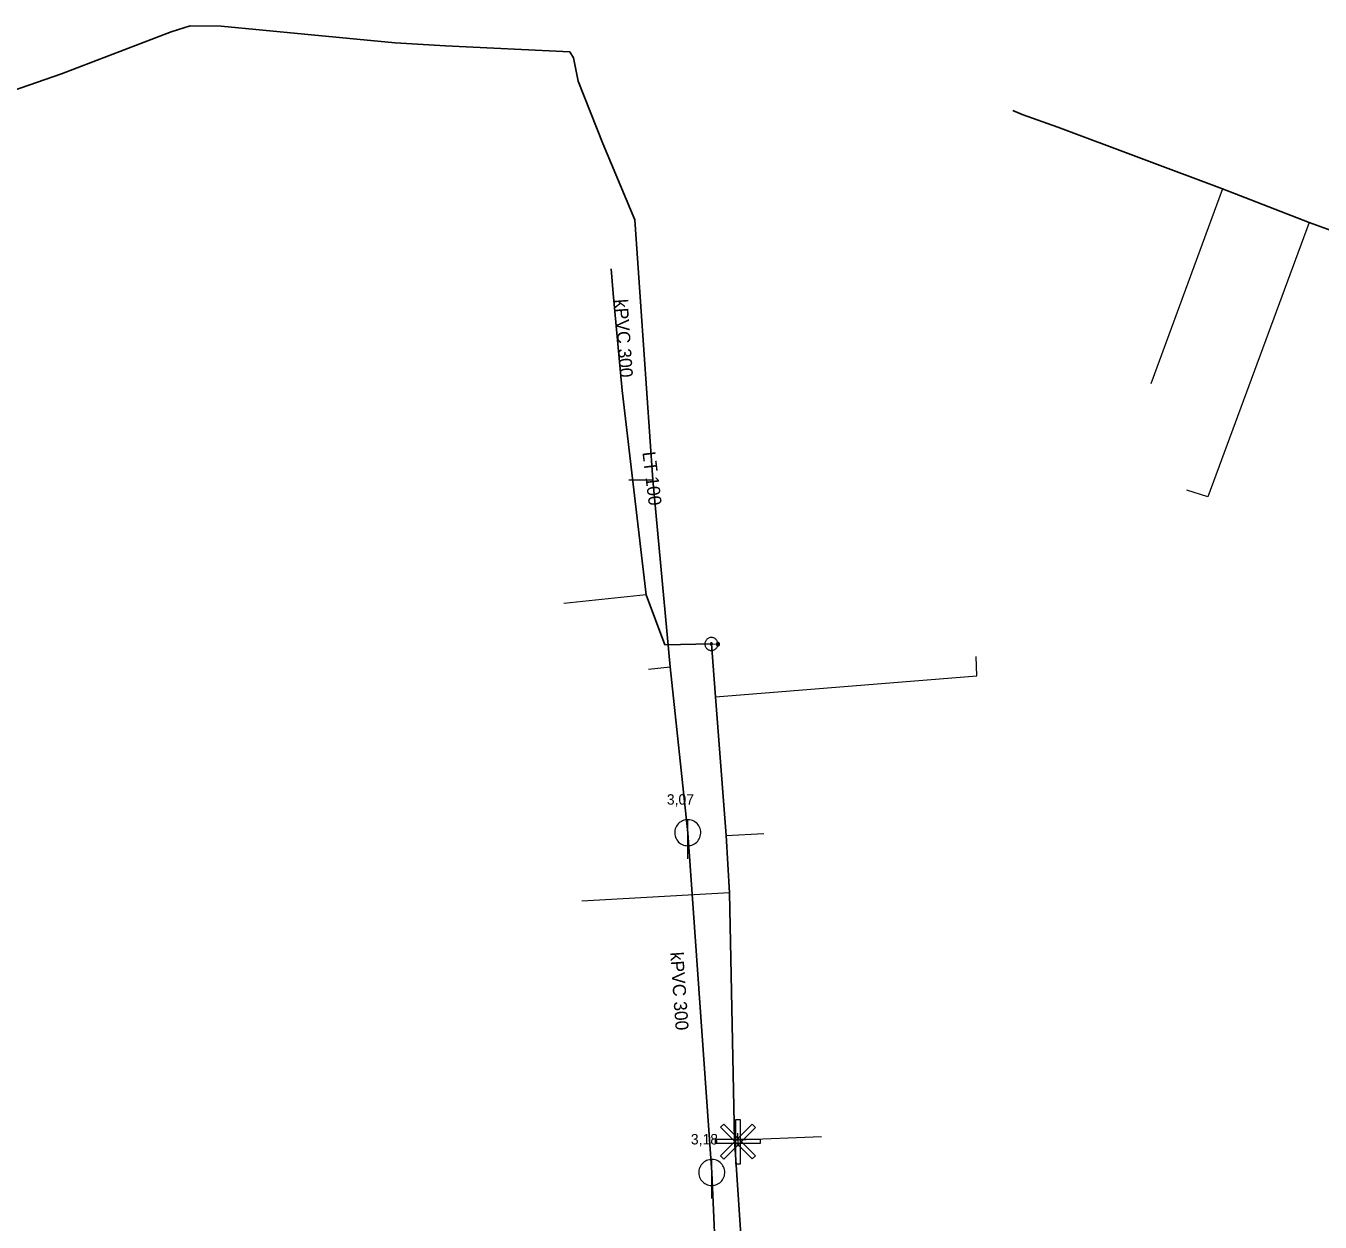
# Model space of a CAD drawing. Extents: x -809916 to -809489, y -991143 to -990912.
# Drawn here: x -809721.2 to -809621.9, y -991005.4 to -990913.7 of the extents above; entities that cross this region are included whole.
import ezdxf

# ---------------------------------------------------------------- set-up
doc = ezdxf.new("R2010")
doc.units = 0
doc.header["$LTSCALE"] = 0.32
doc.layers.add('1', color=7, linetype='Continuous')
for name, color, linetype, lineweight in [('11', 7, 'Continuous', 13), ('12', 7, 'Continuous', 13), ('13', 7, 'Continuous', 13), ('14', 7, 'Continuous', 25), ('17', 7, 'Continuous', 25), ('22', 7, 'Continuous', 13), ('34', 7, 'Continuous', 13), ('47', 7, 'Continuous', 13), ('9', 7, 'Continuous', 13)]:
    doc.layers.add(name, color=color, linetype=linetype, lineweight=lineweight)

msp = doc.modelspace()

# ---------------------------------------------------------------- linework, layer by layer
at = {"layer": '11'}
for p, q in [((-809674.932, -990948.515), (-809673.085, -990948.515)), ((-809673.438, -990963.031), (-809671.767, -990962.855))]:
    msp.add_line(p, q, dxfattribs=at)
at = {"layer": '12'}
for points in [[(-809666.74, -990997.569), (-809666.39, -990997.569), (-809666.39, -991001.004), (-809666.74, -991001.004)], [(-809665.474, -990997.933), (-809665.226, -990998.181), (-809667.655, -991000.61), (-809667.902, -991000.362)], [(-809667.893, -990998.172), (-809667.646, -990997.924), (-809665.217, -991000.353), (-809665.464, -991000.601)], [(-809664.856, -990999.078), (-809664.856, -990999.428), (-809668.291, -990999.428), (-809668.291, -990999.078)]]:
    msp.add_lwpolyline(points, close=True, dxfattribs=at)
at = {"layer": '13'}
for p, q in [((-809629.397, -990926.193), (-809634.882, -990941.14)), ((-809673.607, -990957.328), (-809679.934, -990958.002)), ((-809667.463, -990975.799), (-809664.581, -990975.642)), ((-809667.227, -990980.191), (-809678.553, -990980.828)), ((-809666.587, -990999.127), (-809660.149, -990998.87))]:
    msp.add_line(p, q, dxfattribs=at)
for points in [[(-809622.739, -990928.776), (-809630.51, -990949.821), (-809632.129, -990949.303)], [(-809668.286, -990965.145), (-809648.23, -990963.541), (-809648.283, -990962.051)]]:
    msp.add_lwpolyline(points, dxfattribs=at)
at = {"layer": '14', "lineweight": 13}
for p, q in [((-809668.606, -990961.097), (-809668.099, -990961.112)), ((-809666.831, -990999.127), (-809666.587, -990999.127))]:
    msp.add_line(p, q, dxfattribs=at)
at = {"layer": '14'}
for points in [[(-809726.219, -990969.96), (-809726.98, -990968.78), (-809727.949, -990966.71), (-809728.3, -990955.809), (-809728.739, -990943.25), (-809729.199, -990930.399), (-809729.739, -990922.109), (-809729.96, -990921.489), (-809724.76, -990919.53), (-809718.469, -990917.359), (-809710.05, -990914.129), (-809708.579, -990913.68), (-809706.219, -990913.69), (-809699.82, -990914.32), (-809692.859, -990914.989), (-809688.989, -990915.219), (-809679.469, -990915.67), (-809679.19, -990916.14), (-809678.829, -990917.93), (-809676.92, -990922.699), (-809676.27, -990924.289), (-809674.469, -990928.55)], [(-809674.469, -990928.55), (-809673.085, -990948.515), (-809671.767, -990962.855), (-809670.422, -990975.576), (-809668.578, -991001.644)], [(-809668.578, -991001.644), (-809668.193, -991010.278), (-809666.649, -991030.266), (-809666.449, -991032.861), (-809665.71, -991042.44)]]:
    msp.add_lwpolyline(points, dxfattribs=at)
at = {"layer": '17'}
for points in [[(-809571.565, -990948.231), (-809594.739, -990939.588), (-809604.59, -990935.559), (-809609.82, -990933.473), (-809622.739, -990928.776), (-809629.397, -990926.193), (-809642.024, -990921.442), (-809644.754, -990920.484), (-809645.469, -990920.17)], [(-809668.606, -990961.097), (-809672.164, -990961.159), (-809673.607, -990957.328), (-809675.453, -990941.651), (-809676.144, -990934.199), (-809676.289, -990932.309)], [(-809663.12, -991049.689), (-809663.328, -991047.82), (-809664.033, -991041.203), (-809664.17, -991039.14), (-809664.559, -991033.289), (-809666.831, -990999.127), (-809667.227, -990980.191), (-809667.463, -990975.798), (-809668.285, -990965.145), (-809668.606, -990961.097)]]:
    msp.add_lwpolyline(points, dxfattribs=at)
at = {"layer": '22'}
for p, q in [((-809670.422, -990977.576), (-809670.421, -990974.576)), ((-809668.578, -991003.644), (-809668.577, -991000.644))]:
    msp.add_line(p, q, dxfattribs=at)
for points in [[(-809669.422, -990975.576), (-809669.427, -990975.467), (-809669.445, -990975.359), (-809669.475, -990975.253), (-809669.515, -990975.152), (-809669.567, -990975.055), (-809669.629, -990974.965), (-809669.701, -990974.882), (-809669.781, -990974.808), (-809669.869, -990974.742), (-809669.963, -990974.687), (-809670.063, -990974.642), (-809670.168, -990974.609), (-809670.275, -990974.587), (-809670.384, -990974.577), (-809670.494, -990974.579), (-809670.602, -990974.593), (-809670.709, -990974.618), (-809670.812, -990974.655), (-809670.91, -990974.704), (-809671.002, -990974.762), (-809671.088, -990974.831), (-809671.165, -990974.908), (-809671.234, -990974.994), (-809671.293, -990975.086), (-809671.341, -990975.184), (-809671.378, -990975.287), (-809671.404, -990975.394), (-809671.418, -990975.502), (-809671.421, -990975.612), (-809671.411, -990975.721), (-809671.39, -990975.828), (-809671.356, -990975.932), (-809671.312, -990976.032), (-809671.257, -990976.127), (-809671.191, -990976.215), (-809671.117, -990976.295), (-809671.034, -990976.367), (-809670.944, -990976.429), (-809670.848, -990976.481), (-809670.746, -990976.522), (-809670.641, -990976.552), (-809670.533, -990976.57), (-809670.423, -990976.576), (-809670.314, -990976.57), (-809670.206, -990976.552), (-809670.101, -990976.523), (-809669.999, -990976.482), (-809669.902, -990976.43), (-809669.812, -990976.368), (-809669.729, -990976.297), (-809669.654, -990976.217), (-809669.589, -990976.129), (-809669.533, -990976.035), (-809669.489, -990975.935), (-809669.455, -990975.831), (-809669.433, -990975.723), (-809669.423, -990975.614)], [(-809667.578, -991001.644), (-809667.583, -991001.535), (-809667.601, -991001.427), (-809667.631, -991001.321), (-809667.671, -991001.22), (-809667.723, -991001.123), (-809667.785, -991001.033), (-809667.857, -991000.95), (-809667.937, -991000.876), (-809668.025, -991000.81), (-809668.119, -991000.755), (-809668.219, -991000.71), (-809668.324, -991000.677), (-809668.431, -991000.655), (-809668.54, -991000.645), (-809668.65, -991000.647), (-809668.758, -991000.661), (-809668.865, -991000.686), (-809668.968, -991000.723), (-809669.066, -991000.772), (-809669.158, -991000.83), (-809669.244, -991000.899), (-809669.321, -991000.976), (-809669.39, -991001.062), (-809669.449, -991001.154), (-809669.497, -991001.252), (-809669.534, -991001.355), (-809669.56, -991001.462), (-809669.574, -991001.57), (-809669.577, -991001.68), (-809669.567, -991001.789), (-809669.546, -991001.896), (-809669.512, -991002), (-809669.468, -991002.1), (-809669.413, -991002.195), (-809669.347, -991002.283), (-809669.273, -991002.363), (-809669.19, -991002.435), (-809669.1, -991002.497), (-809669.004, -991002.549), (-809668.902, -991002.59), (-809668.797, -991002.62), (-809668.689, -991002.638), (-809668.579, -991002.644), (-809668.47, -991002.638), (-809668.362, -991002.62), (-809668.257, -991002.591), (-809668.155, -991002.55), (-809668.058, -991002.498), (-809667.968, -991002.436), (-809667.885, -991002.365), (-809667.81, -991002.285), (-809667.745, -991002.197), (-809667.689, -991002.103), (-809667.645, -991002.003), (-809667.611, -991001.899), (-809667.589, -991001.791), (-809667.579, -991001.682)]]:
    msp.add_lwpolyline(points, close=True, dxfattribs=at)
at = {"layer": '34'}
msp.add_line((-809666.607, -990998.627), (-809666.567, -990999.626), dxfattribs=at)
at = {"layer": '47'}
for points in [[(-809668.106, -990961.088), (-809668.109, -990961.036), (-809668.118, -990960.984), (-809668.133, -990960.934), (-809668.152, -990960.886), (-809668.177, -990960.839), (-809668.207, -990960.796), (-809668.24, -990960.756), (-809668.278, -990960.72), (-809668.318, -990960.688), (-809668.363, -990960.659), (-809668.41, -990960.636), (-809668.46, -990960.619), (-809668.51, -990960.606), (-809668.562, -990960.599), (-809668.614, -990960.597), (-809668.666, -990960.6), (-809668.718, -990960.609), (-809668.769, -990960.624), (-809668.816, -990960.643), (-809668.863, -990960.668), (-809668.906, -990960.698), (-809668.947, -990960.731), (-809668.983, -990960.769), (-809669.015, -990960.809), (-809669.043, -990960.854), (-809669.066, -990960.901), (-809669.084, -990960.951), (-809669.096, -990961.001), (-809669.103, -990961.053), (-809669.105, -990961.105), (-809669.102, -990961.157), (-809669.093, -990961.209), (-809669.079, -990961.26), (-809669.059, -990961.307), (-809669.034, -990961.354), (-809669.005, -990961.397), (-809668.972, -990961.438), (-809668.934, -990961.474), (-809668.893, -990961.506), (-809668.848, -990961.534), (-809668.801, -990961.557), (-809668.752, -990961.575), (-809668.701, -990961.587), (-809668.649, -990961.594), (-809668.597, -990961.596), (-809668.545, -990961.593), (-809668.493, -990961.584), (-809668.443, -990961.57), (-809668.395, -990961.55), (-809668.348, -990961.525), (-809668.305, -990961.496), (-809668.265, -990961.463), (-809668.229, -990961.425), (-809668.197, -990961.384), (-809668.168, -990961.339), (-809668.145, -990961.292), (-809668.128, -990961.243), (-809668.115, -990961.192), (-809668.108, -990961.14)], [(-809668.524, -990961.095), (-809668.524, -990961.086), (-809668.526, -990961.078), (-809668.528, -990961.07), (-809668.531, -990961.062), (-809668.535, -990961.054), (-809668.54, -990961.047), (-809668.545, -990961.04), (-809668.552, -990961.035), (-809668.559, -990961.03), (-809668.566, -990961.025), (-809668.574, -990961.021), (-809668.582, -990961.018), (-809668.59, -990961.016), (-809668.598, -990961.014), (-809668.607, -990961.015), (-809668.616, -990961.015), (-809668.624, -990961.017), (-809668.632, -990961.019), (-809668.64, -990961.022), (-809668.648, -990961.026), (-809668.655, -990961.031), (-809668.662, -990961.036), (-809668.667, -990961.043), (-809668.673, -990961.05), (-809668.677, -990961.057), (-809668.681, -990961.065), (-809668.684, -990961.073), (-809668.686, -990961.081), (-809668.688, -990961.089), (-809668.687, -990961.098), (-809668.687, -990961.107), (-809668.685, -990961.115), (-809668.683, -990961.123), (-809668.68, -990961.131), (-809668.676, -990961.139), (-809668.672, -990961.146), (-809668.666, -990961.153), (-809668.659, -990961.158), (-809668.652, -990961.164), (-809668.645, -990961.168), (-809668.637, -990961.172), (-809668.629, -990961.175), (-809668.621, -990961.177), (-809668.613, -990961.179), (-809668.604, -990961.178), (-809668.595, -990961.178), (-809668.587, -990961.176), (-809668.579, -990961.174), (-809668.571, -990961.171), (-809668.563, -990961.167), (-809668.556, -990961.163), (-809668.549, -990961.157), (-809668.544, -990961.15), (-809668.539, -990961.143), (-809668.534, -990961.136), (-809668.53, -990961.128), (-809668.527, -990961.12), (-809668.525, -990961.112), (-809668.523, -990961.104)]]:
    msp.add_lwpolyline(points, close=True, dxfattribs=at)
at = {"layer": '9'}
for points in [[(-809668.225, -990961.112), (-809668.225, -990961.125), (-809668.223, -990961.138), (-809668.22, -990961.151), (-809668.215, -990961.163), (-809668.209, -990961.175), (-809668.202, -990961.186), (-809668.194, -990961.196), (-809668.184, -990961.206), (-809668.174, -990961.214), (-809668.163, -990961.221), (-809668.151, -990961.227), (-809668.139, -990961.232), (-809668.126, -990961.235), (-809668.113, -990961.237), (-809668.1, -990961.239), (-809668.087, -990961.238), (-809668.074, -990961.236), (-809668.061, -990961.233), (-809668.049, -990961.228), (-809668.037, -990961.222), (-809668.026, -990961.215), (-809668.016, -990961.207), (-809668.006, -990961.197), (-809667.998, -990961.187), (-809667.991, -990961.176), (-809667.985, -990961.164), (-809667.98, -990961.152), (-809667.977, -990961.139), (-809667.975, -990961.126), (-809667.973, -990961.113), (-809667.974, -990961.1), (-809667.976, -990961.087), (-809667.979, -990961.074), (-809667.984, -990961.062), (-809667.99, -990961.05), (-809667.997, -990961.039), (-809668.005, -990961.029), (-809668.015, -990961.019), (-809668.025, -990961.011), (-809668.036, -990961.004), (-809668.048, -990960.998), (-809668.06, -990960.993), (-809668.073, -990960.99), (-809668.086, -990960.988), (-809668.099, -990960.987), (-809668.112, -990960.987), (-809668.125, -990960.989), (-809668.138, -990960.992), (-809668.15, -990960.997), (-809668.162, -990961.003), (-809668.173, -990961.01), (-809668.183, -990961.018), (-809668.193, -990961.028), (-809668.201, -990961.038), (-809668.208, -990961.049), (-809668.214, -990961.061), (-809668.219, -990961.073), (-809668.222, -990961.086), (-809668.224, -990961.099)], [(-809668.205, -990961.112), (-809668.206, -990961.123), (-809668.204, -990961.134), (-809668.201, -990961.145), (-809668.197, -990961.155), (-809668.192, -990961.165), (-809668.186, -990961.174), (-809668.179, -990961.183), (-809668.171, -990961.191), (-809668.162, -990961.198), (-809668.153, -990961.204), (-809668.143, -990961.209), (-809668.133, -990961.213), (-809668.122, -990961.216), (-809668.111, -990961.219), (-809668.1, -990961.219), (-809668.089, -990961.219), (-809668.078, -990961.217), (-809668.067, -990961.214), (-809668.057, -990961.21), (-809668.047, -990961.205), (-809668.038, -990961.199), (-809668.029, -990961.192), (-809668.021, -990961.184), (-809668.014, -990961.175), (-809668.008, -990961.166), (-809668.003, -990961.156), (-809667.999, -990961.146), (-809667.996, -990961.135), (-809667.994, -990961.124), (-809667.993, -990961.113), (-809667.993, -990961.102), (-809667.995, -990961.091), (-809667.998, -990961.08), (-809668.002, -990961.07), (-809668.007, -990961.06), (-809668.013, -990961.051), (-809668.02, -990961.042), (-809668.028, -990961.034), (-809668.037, -990961.027), (-809668.046, -990961.021), (-809668.056, -990961.016), (-809668.066, -990961.012), (-809668.077, -990961.009), (-809668.088, -990961.007), (-809668.099, -990961.007), (-809668.11, -990961.006), (-809668.121, -990961.008), (-809668.132, -990961.011), (-809668.142, -990961.015), (-809668.152, -990961.02), (-809668.161, -990961.026), (-809668.17, -990961.033), (-809668.178, -990961.041), (-809668.185, -990961.05), (-809668.191, -990961.059), (-809668.196, -990961.069), (-809668.2, -990961.079), (-809668.203, -990961.09), (-809668.205, -990961.101)], [(-809668.186, -990961.112), (-809668.186, -990961.121), (-809668.185, -990961.13), (-809668.182, -990961.139), (-809668.179, -990961.147), (-809668.175, -990961.155), (-809668.17, -990961.163), (-809668.164, -990961.17), (-809668.158, -990961.176), (-809668.151, -990961.182), (-809668.143, -990961.187), (-809668.135, -990961.191), (-809668.127, -990961.194), (-809668.118, -990961.197), (-809668.109, -990961.198), (-809668.1, -990961.2), (-809668.091, -990961.199), (-809668.082, -990961.198), (-809668.073, -990961.195), (-809668.065, -990961.192), (-809668.057, -990961.188), (-809668.049, -990961.183), (-809668.042, -990961.177), (-809668.036, -990961.171), (-809668.03, -990961.164), (-809668.025, -990961.156), (-809668.021, -990961.148), (-809668.018, -990961.14), (-809668.015, -990961.131), (-809668.014, -990961.122), (-809668.012, -990961.113), (-809668.013, -990961.104), (-809668.014, -990961.095), (-809668.017, -990961.086), (-809668.02, -990961.078), (-809668.024, -990961.07), (-809668.029, -990961.062), (-809668.035, -990961.055), (-809668.041, -990961.049), (-809668.048, -990961.043), (-809668.056, -990961.038), (-809668.064, -990961.034), (-809668.072, -990961.031), (-809668.081, -990961.028), (-809668.09, -990961.027), (-809668.099, -990961.026), (-809668.108, -990961.026), (-809668.117, -990961.027), (-809668.126, -990961.03), (-809668.134, -990961.033), (-809668.142, -990961.037), (-809668.15, -990961.042), (-809668.157, -990961.048), (-809668.163, -990961.054), (-809668.169, -990961.061), (-809668.174, -990961.069), (-809668.178, -990961.077), (-809668.181, -990961.085), (-809668.184, -990961.094), (-809668.185, -990961.103)], [(-809668.166, -990961.112), (-809668.166, -990961.119), (-809668.165, -990961.126), (-809668.164, -990961.133), (-809668.161, -990961.139), (-809668.158, -990961.145), (-809668.154, -990961.151), (-809668.15, -990961.157), (-809668.145, -990961.162), (-809668.139, -990961.166), (-809668.133, -990961.17), (-809668.127, -990961.173), (-809668.121, -990961.176), (-809668.114, -990961.177), (-809668.107, -990961.18), (-809668.1, -990961.18), (-809668.093, -990961.18), (-809668.086, -990961.178), (-809668.079, -990961.177), (-809668.073, -990961.174), (-809668.066, -990961.171), (-809668.061, -990961.167), (-809668.055, -990961.163), (-809668.05, -990961.158), (-809668.046, -990961.152), (-809668.042, -990961.146), (-809668.039, -990961.14), (-809668.036, -990961.134), (-809668.034, -990961.127), (-809668.033, -990961.12), (-809668.032, -990961.113), (-809668.032, -990961.106), (-809668.033, -990961.099), (-809668.035, -990961.092), (-809668.038, -990961.086), (-809668.041, -990961.079), (-809668.045, -990961.074), (-809668.049, -990961.068), (-809668.054, -990961.063), (-809668.06, -990961.059), (-809668.065, -990961.055), (-809668.072, -990961.052), (-809668.078, -990961.049), (-809668.085, -990961.047), (-809668.092, -990961.046), (-809668.099, -990961.046), (-809668.106, -990961.046), (-809668.113, -990961.046), (-809668.12, -990961.048), (-809668.126, -990961.051), (-809668.132, -990961.054), (-809668.138, -990961.058), (-809668.144, -990961.062), (-809668.149, -990961.067), (-809668.153, -990961.073), (-809668.157, -990961.078), (-809668.16, -990961.085), (-809668.163, -990961.091), (-809668.164, -990961.098), (-809668.166, -990961.105)], [(-809668.146, -990961.112), (-809668.146, -990961.117), (-809668.146, -990961.122), (-809668.145, -990961.127), (-809668.143, -990961.131), (-809668.141, -990961.136), (-809668.138, -990961.14), (-809668.135, -990961.143), (-809668.131, -990961.147), (-809668.128, -990961.15), (-809668.124, -990961.153), (-809668.119, -990961.155), (-809668.115, -990961.157), (-809668.11, -990961.158), (-809668.105, -990961.16), (-809668.1, -990961.16), (-809668.095, -990961.16), (-809668.09, -990961.159), (-809668.085, -990961.158), (-809668.081, -990961.156), (-809668.076, -990961.154), (-809668.072, -990961.151), (-809668.068, -990961.148), (-809668.065, -990961.144), (-809668.062, -990961.141), (-809668.059, -990961.137), (-809668.057, -990961.132), (-809668.055, -990961.128), (-809668.054, -990961.123), (-809668.053, -990961.118), (-809668.052, -990961.113), (-809668.052, -990961.108), (-809668.053, -990961.103), (-809668.054, -990961.098), (-809668.056, -990961.094), (-809668.058, -990961.089), (-809668.061, -990961.085), (-809668.064, -990961.081), (-809668.067, -990961.078), (-809668.071, -990961.075), (-809668.075, -990961.072), (-809668.08, -990961.07), (-809668.084, -990961.068), (-809668.089, -990961.067), (-809668.094, -990961.066), (-809668.099, -990961.066), (-809668.104, -990961.066), (-809668.109, -990961.067), (-809668.114, -990961.067), (-809668.118, -990961.069), (-809668.123, -990961.071), (-809668.127, -990961.074), (-809668.13, -990961.077), (-809668.134, -990961.08), (-809668.137, -990961.084), (-809668.14, -990961.088), (-809668.142, -990961.093), (-809668.144, -990961.097), (-809668.145, -990961.102), (-809668.146, -990961.107)], [(-809668.126, -990961.112), (-809668.126, -990961.115), (-809668.127, -990961.118), (-809668.126, -990961.12), (-809668.125, -990961.123), (-809668.124, -990961.126), (-809668.122, -990961.128), (-809668.12, -990961.13), (-809668.118, -990961.132), (-809668.116, -990961.134), (-809668.114, -990961.136), (-809668.111, -990961.138), (-809668.108, -990961.139), (-809668.106, -990961.139), (-809668.103, -990961.14), (-809668.1, -990961.14), (-809668.097, -990961.14), (-809668.094, -990961.14), (-809668.091, -990961.139), (-809668.089, -990961.138), (-809668.086, -990961.137), (-809668.084, -990961.135), (-809668.081, -990961.133), (-809668.079, -990961.131), (-809668.078, -990961.129), (-809668.076, -990961.127), (-809668.075, -990961.124), (-809668.073, -990961.121), (-809668.073, -990961.119), (-809668.072, -990961.116), (-809668.071, -990961.113), (-809668.072, -990961.11), (-809668.072, -990961.107), (-809668.073, -990961.104), (-809668.074, -990961.102), (-809668.075, -990961.099), (-809668.077, -990961.097), (-809668.078, -990961.094), (-809668.08, -990961.092), (-809668.083, -990961.091), (-809668.085, -990961.089), (-809668.088, -990961.088), (-809668.09, -990961.087), (-809668.093, -990961.086), (-809668.096, -990961.086), (-809668.099, -990961.085), (-809668.102, -990961.086), (-809668.105, -990961.085), (-809668.107, -990961.087), (-809668.11, -990961.087), (-809668.113, -990961.088), (-809668.115, -990961.09), (-809668.117, -990961.091), (-809668.119, -990961.093), (-809668.121, -990961.096), (-809668.123, -990961.098), (-809668.124, -990961.101), (-809668.125, -990961.103), (-809668.126, -990961.106), (-809668.126, -990961.109)], [(-809668.107, -990961.112), (-809668.107, -990961.114), (-809668.107, -990961.114), (-809668.106, -990961.114), (-809668.106, -990961.116), (-809668.107, -990961.117), (-809668.105, -990961.117), (-809668.105, -990961.117), (-809668.105, -990961.119), (-809668.105, -990961.119), (-809668.104, -990961.12), (-809668.102, -990961.12), (-809668.102, -990961.12), (-809668.102, -990961.121), (-809668.1, -990961.121), (-809668.1, -990961.121), (-809668.099, -990961.121), (-809668.098, -990961.121), (-809668.098, -990961.12), (-809668.097, -990961.12), (-809668.095, -990961.12), (-809668.095, -990961.119), (-809668.095, -990961.119), (-809668.094, -990961.118), (-809668.094, -990961.118), (-809668.092, -990961.117), (-809668.092, -990961.116), (-809668.091, -990961.115), (-809668.091, -990961.115), (-809668.091, -990961.114), (-809668.091, -990961.113), (-809668.091, -990961.112), (-809668.091, -990961.111), (-809668.091, -990961.111), (-809668.092, -990961.11), (-809668.092, -990961.109), (-809668.093, -990961.108), (-809668.093, -990961.108), (-809668.094, -990961.107), (-809668.094, -990961.107), (-809668.095, -990961.106), (-809668.096, -990961.106), (-809668.097, -990961.105), (-809668.097, -990961.105), (-809668.098, -990961.105), (-809668.099, -990961.105), (-809668.1, -990961.105), (-809668.101, -990961.105), (-809668.101, -990961.105), (-809668.102, -990961.106), (-809668.103, -990961.105), (-809668.104, -990961.107), (-809668.104, -990961.107), (-809668.105, -990961.107), (-809668.105, -990961.107), (-809668.106, -990961.109), (-809668.106, -990961.11), (-809668.106, -990961.111), (-809668.107, -990961.111), (-809668.107, -990961.112)]]:
    msp.add_lwpolyline(points, close=True, dxfattribs=at)

# ---------------------------------------------------------------- texts
at = {"layer": '1'}
for s, rotation, p in [('kPVC 300', 274, (-809676.034, -990934.679)), ('LT 100', 277, (-809673.902, -990946.394)), ('kPVC 300', 274, (-809671.762, -990984.76))]:
    msp.add_text(s, height=1, rotation=rotation, dxfattribs=at).set_placement(p)
for s, p in [('3,07', (-809672.022, -990973.424)), ('3,18', (-809670.178, -990999.492))]:
    msp.add_text(s, height=0.8, dxfattribs=at).set_placement(p)

doc.saveas('drawing.dxf')
